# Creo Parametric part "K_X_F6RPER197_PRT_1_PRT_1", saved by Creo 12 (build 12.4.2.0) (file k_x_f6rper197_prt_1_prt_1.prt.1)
Units: Custom; MM, KILOGRAM, SECS

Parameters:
  PTC_WM_ITERATION = "0"
  PTC_WM_VERSION = "-.0"
  PTC_WM_LIFECYCLE_STATE = "In Work"
  PTC_WM_LIFECYCLE = "MO_CADDocument"
  PTC_WM_CREATED_BY = "Maximilian Roepper (Z0017RMS: MO)"
  PTC_WM_CREATED_ON = "18-Sep-26 11:36:42 AM"
  PTC_WM_MODIFIED_BY = "Maximilian Roepper (Z0017RMS: MO)"
  PTC_WM_MODIFIED_ON = "18-Sep-26 11:36:46 AM"
  PDMLINKNUMBER = "PDM000071454928"
  PTC_WM_NAME = "k_x_f6rper197_prt_1_prt_1.prt"
  PTC_WM_NUMBER = "PDM000071454928"

Other parameters: WEIGHT, WEIGHT_FACTOR, WEIGHT_ADD, _MASS_TEMP, _DIFF_TEMP, MC_ERRORS, SUPPLIER

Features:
  1. coordinate system
  2. datum plane "PRT_YZ"
  3. datum plane "PRT_XY"
  4. datum plane "PRT_XZ"
  5. coordinate system
  6. datum axis
  7. datum axis
  8. datum axis
  9. coordinate system
  10. imported feature
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
Other named items: PRT, SIEMENS_MO, DRW_VIEW_ORG, PRT_X, PRT_Y, PRT_Z, CS0, ROUGH_GROB

Layers: 00_STD_CSYS-KSYS, 01_STD_PLANES-EBENEN, 02_STD_AXES-ACHSEN, 03_STD_CSYS-KSYS, 24_IMPORT_FEAT-IMPORT_KE

Surfaces: 6 plane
